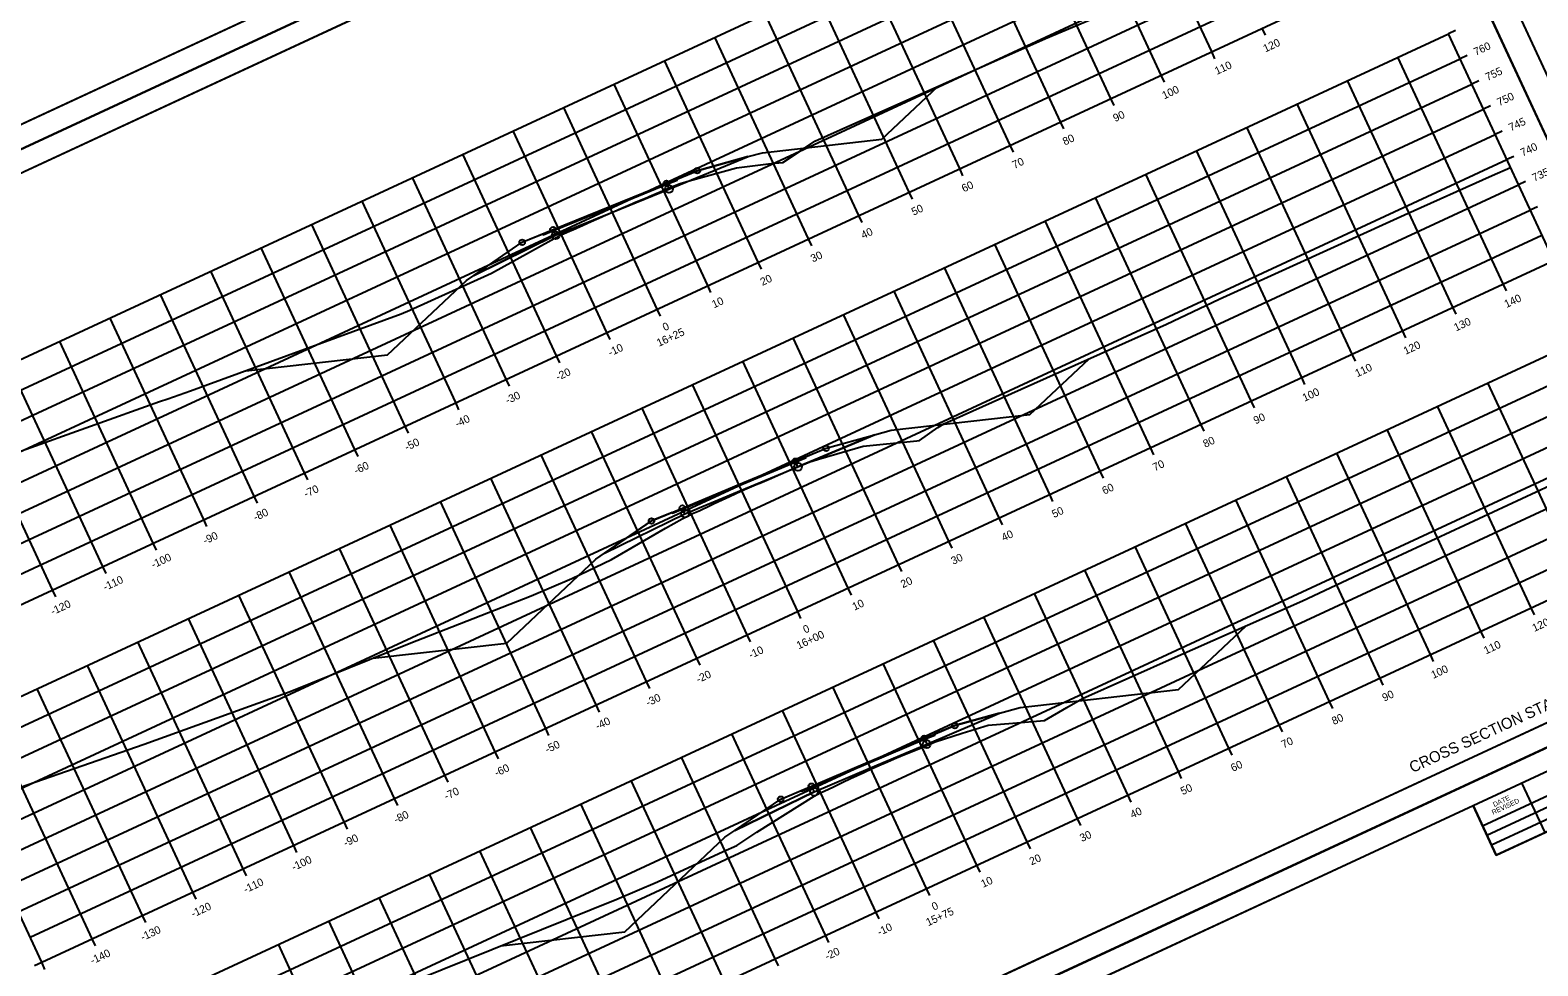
# Model space of a CAD drawing. Extents: x 1354696 to 1366163, y 660729 to 670380.
# Drawn here: x 1358666.2 to 1358937.5, y 666178.8 to 666347.2 of the extents above; entities that cross this region are included whole.
import ezdxf

# ---------------------------------------------------------------- set-up
doc = ezdxf.new("R2010")
doc.units = 0
for name, color, linetype in [('R_Alt Surface', 7, 'Continuous'), ('R_Axis', 7, 'Continuous'), ('R_Axis Annot', 7, 'Continuous'), ('R_Border', 7, 'Continuous'), ('R_Draft', 7, 'Continuous'), ('R_Exist Surface', 7, 'Continuous'), ('R_Fin Surface', 7, 'Continuous'), ('R_Grid', 7, 'Continuous'), ('R_No Plot', 7, 'Continuous')]:
    doc.layers.add(name, color=color, linetype=linetype)

msp = doc.modelspace()

# ---------------------------------------------------------------- linework, layer by layer
at = {"layer": 'R_Alt Surface'}
for p, q in [((1358780.65, 666319.63), (1358782.5, 666320.38)), ((1358780.72, 666319.47), (1358782.57, 666320.23)), ((1358758.42, 666310.55), (1358760.26, 666311.3)), ((1358758.49, 666310.39), (1358760.33, 666311.15)), ((1358803.86, 666269.64), (1358805.7, 666270.41)), ((1358803.93, 666269.49), (1358805.77, 666270.26)), ((1358781.69, 666260.42), (1358783.53, 666261.19)), ((1358781.76, 666260.27), (1358783.6, 666261.03)), ((1358827.03, 666219.73), (1358828.88, 666220.5)), ((1358827.1, 666219.57), (1358828.96, 666220.34)), ((1358804.93, 666210.36), (1358806.76, 666211.14)), ((1358805, 666210.21), (1358806.83, 666210.98))]:
    msp.add_line(p, q, dxfattribs=at)
for points in [[(1358745.99, 666303.07), (1358760.73, 666310.28), (1358770.93, 666314.44), (1358781.12, 666318.61), (1358795.4, 666324.44)], [(1358760.26, 666311.3), (1358770.45, 666315.46), (1358780.65, 666319.63)], [(1358760.33, 666311.15), (1358770.53, 666315.31), (1358780.72, 666319.47)], [(1358769.49, 666253.07), (1358784, 666260.17), (1358794.16, 666264.39), (1358804.33, 666268.62), (1358818.11, 666274.36)], [(1358783.53, 666261.19), (1358793.69, 666265.41), (1358803.86, 666269.64)], [(1358783.6, 666261.03), (1358793.76, 666265.26), (1358803.93, 666269.49)], [(1358792.97, 666203.14), (1358807.24, 666210.12), (1358817.37, 666214.41), (1358827.5, 666218.7), (1358840.58, 666224.25)], [(1358806.76, 666211.14), (1358816.9, 666215.43), (1358827.03, 666219.73)], [(1358806.83, 666210.98), (1358816.97, 666215.28), (1358827.1, 666219.57)]]:
    msp.add_lwpolyline(points, dxfattribs=at)
for points in [[(1358782.5, 666320.38), (1358782.57, 666320.23), (1358780.72, 666319.47), (1358781.12, 666318.61), (1358795.4, 666324.44), (1358786.21, 666321.9)], [(1358758.42, 666310.55), (1358758.49, 666310.39), (1358760.33, 666311.15), (1358760.73, 666310.28), (1358745.99, 666303.07), (1358754.7, 666309.03)], [(1358805.7, 666270.41), (1358809.4, 666271.95), (1358818.11, 666274.36), (1358804.33, 666268.62), (1358803.93, 666269.49), (1358805.77, 666270.26)], [(1358781.69, 666260.42), (1358777.98, 666258.88), (1358769.49, 666253.07), (1358784, 666260.17), (1358783.6, 666261.03), (1358781.76, 666260.27)], [(1358828.88, 666220.5), (1358828.96, 666220.34), (1358827.1, 666219.57), (1358827.5, 666218.7), (1358840.58, 666224.25), (1358832.57, 666222.03)], [(1358804.93, 666210.36), (1358805, 666210.21), (1358806.83, 666210.98), (1358807.24, 666210.12), (1358792.97, 666203.14), (1358801.24, 666208.79)]]:
    msp.add_lwpolyline(points, close=True, dxfattribs=at)
at = {"layer": 'R_Axis'}
for p, q in [((1358642.97, 666233.85), (1358915.07, 666360.18)), ((1358888.45, 666346.28), (1358887.86, 666347.55)), ((1358922.66, 666347.16), (1358921.39, 666346.57)), ((1358940.34, 666305.76), (1358921.39, 666346.57)), ((1358879.38, 666342.07), (1358878.79, 666343.34)), ((1358924.76, 666342.63), (1358923.49, 666342.04)), ((1358870.31, 666337.85), (1358869.72, 666339.12)), ((1358926.87, 666338.09), (1358925.6, 666337.5)), ((1358861.24, 666333.64), (1358860.65, 666334.91)), ((1358928.97, 666333.56), (1358927.7, 666332.97)), ((1358852.17, 666329.43), (1358851.58, 666330.7)), ((1358931.08, 666329.02), (1358929.81, 666328.43)), ((1358843.1, 666325.22), (1358842.51, 666326.49)), ((1358834.03, 666321.01), (1358833.44, 666322.28)), ((1358933.19, 666324.49), (1358931.92, 666323.9)), ((1358935.29, 666319.95), (1358934.02, 666319.36)), ((1358824.96, 666316.8), (1358824.37, 666318.07)), ((1358815.89, 666312.59), (1358815.3, 666313.86)), ((1358937.4, 666315.42), (1358936.13, 666314.83)), ((1358806.82, 666308.38), (1358806.23, 666309.65)), ((1358668.23, 666179.43), (1358940.34, 666305.76)), ((1358797.75, 666304.17), (1358797.16, 666305.44)), ((1358788.68, 666299.96), (1358788.09, 666301.23)), ((1358931.86, 666300.28), (1358931.27, 666301.55)), ((1358779.61, 666295.74), (1358779.02, 666297.01)), ((1358922.79, 666296.07), (1358922.2, 666297.34)), ((1358770.54, 666291.53), (1358769.95, 666292.8)), ((1358913.72, 666291.86), (1358913.13, 666293.13)), ((1358761.47, 666287.32), (1358760.88, 666288.59)), ((1358904.65, 666287.65), (1358904.06, 666288.91)), ((1358752.4, 666283.11), (1358751.81, 666284.38)), ((1358895.58, 666283.43), (1358894.99, 666284.7)), ((1358743.33, 666278.9), (1358742.74, 666280.17)), ((1358886.51, 666279.22), (1358885.92, 666280.49)), ((1358734.26, 666274.69), (1358733.67, 666275.96)), ((1358877.44, 666275.01), (1358876.85, 666276.28)), ((1358725.19, 666270.48), (1358724.6, 666271.75)), ((1358868.37, 666270.8), (1358867.78, 666272.07)), ((1358859.3, 666266.59), (1358858.71, 666267.86)), ((1358716.12, 666266.27), (1358715.53, 666267.54)), ((1358707.05, 666262.06), (1358706.46, 666263.33)), ((1358850.23, 666262.38), (1358849.64, 666263.65)), ((1358841.16, 666258.17), (1358840.57, 666259.44)), ((1358697.98, 666257.85), (1358697.39, 666259.12)), ((1358688.91, 666253.63), (1358688.32, 666254.9)), ((1358691.39, 666129.54), (1358963.5, 666255.87)), ((1358832.09, 666253.96), (1358831.5, 666255.23)), ((1358679.84, 666249.42), (1358679.25, 666250.69)), ((1358823.02, 666249.75), (1358822.43, 666251.02)), ((1358670.77, 666245.21), (1358670.18, 666246.48)), ((1358813.95, 666245.53), (1358813.36, 666246.8)), ((1358936.88, 666241.97), (1358936.29, 666243.24)), ((1358804.88, 666241.32), (1358804.29, 666242.59)), ((1358795.81, 666237.11), (1358795.22, 666238.38)), ((1358927.81, 666237.76), (1358927.22, 666239.03)), ((1358786.74, 666232.9), (1358786.15, 666234.17)), ((1358918.74, 666233.55), (1358918.15, 666234.82)), ((1358777.67, 666228.69), (1358777.08, 666229.96)), ((1358909.67, 666229.34), (1358909.08, 666230.61)), ((1358768.59, 666224.48), (1358768.01, 666225.75)), ((1358900.6, 666225.13), (1358900.01, 666226.4)), ((1358759.52, 666220.27), (1358758.94, 666221.54)), ((1358891.53, 666220.92), (1358890.94, 666222.19)), ((1358668.23, 666179.43), (1358649.28, 666220.24)), ((1358750.45, 666216.06), (1358749.87, 666217.33)), ((1358882.46, 666216.7), (1358881.87, 666217.97)), ((1358873.39, 666212.49), (1358872.8, 666213.76)), ((1358741.38, 666211.85), (1358740.8, 666213.12)), ((1358732.31, 666207.64), (1358731.72, 666208.91)), ((1358864.32, 666208.28), (1358863.73, 666209.55)), ((1358855.25, 666204.07), (1358854.66, 666205.34)), ((1358723.24, 666203.42), (1358722.65, 666204.69)), ((1358714.17, 666199.21), (1358713.58, 666200.48)), ((1358846.18, 666199.86), (1358845.59, 666201.13)), ((1358705.1, 666195), (1358704.51, 666196.27)), ((1358837.11, 666195.65), (1358836.52, 666196.92)), ((1358696.03, 666190.79), (1358695.44, 666192.06)), ((1358828.04, 666191.44), (1358827.45, 666192.71)), ((1358686.96, 666186.58), (1358686.37, 666187.85)), ((1358818.97, 666187.23), (1358818.38, 666188.5)), ((1358677.89, 666182.37), (1358677.3, 666183.64)), ((1358809.9, 666183.02), (1358809.31, 666184.29)), ((1358666.96, 666178.84), (1358668.23, 666179.43)), ((1358668.82, 666178.16), (1358668.23, 666179.43)), ((1358800.83, 666178.81), (1358800.24, 666180.07))]:
    msp.add_line(p, q, dxfattribs=at)
at = {"layer": 'R_Border'}
for p, q in [((1358889.5, 666434.68), (1358602.72, 666301.53)), ((1358606.04, 666294.39), (1358892.82, 666427.53)), ((1358979.34, 666241.18), (1358892.82, 666427.53)), ((1358979.34, 666241.18), (1358692.56, 666108.03)), ((1358695.88, 666100.89), (1358982.66, 666234.03)), ((1358986.82, 666225.07), (1358930, 666198.69)), ((1358927.53, 666204.01), (1358945.26, 666212.24)), ((1358938.78, 666202.77), (1358934.62, 666211.73)), ((1358928.32, 666202.32), (1358946.04, 666210.55)), ((1358929.14, 666200.56), (1358946.86, 666208.79)), ((1358930, 666198.69), (1358925.84, 666207.65))]:
    msp.add_line(p, q, dxfattribs=at)
at = {"layer": 'R_Exist Surface'}
for points in [[(1358639.7, 666262.63), (1358689.42, 666280.37), (1358690.94, 666280.84), (1358695.04, 666282.27), (1358732.95, 666296.13), (1358734.5, 666296.83), (1358749.21, 666303.45), (1358753.2, 666305.66), (1358760.47, 666309.72), (1358761.74, 666310.36), (1358761.85, 666310.42), (1358763.66, 666311.2), (1358763.82, 666311.28), (1358766.32, 666312.4), (1358766.55, 666312.51), (1358769.05, 666313.61), (1358769.3, 666313.73), (1358771.78, 666314.83), (1358772.03, 666314.95), (1358774.53, 666315.99), (1358774.8, 666316.1), (1358777.29, 666317.14), (1358777.57, 666317.26), (1358780.8, 666318.66), (1358781.21, 666318.83), (1358781.43, 666318.93), (1358783.13, 666319.63), (1358784.74, 666320.08), (1358793.28, 666322.44), (1358799.51, 666323.2), (1358801.62, 666323.37), (1358806.42, 666326.55), (1358807.4, 666327.22), (1358811.94, 666329.25), (1358848.88, 666345.73), (1358869.14, 666354.3)], [(1358660.03, 666209.45), (1358686.69, 666218.71), (1358712.92, 666228.19), (1358734.39, 666236.79), (1358756.3, 666245.4), (1358763.62, 666248.5), (1358770.78, 666251.93), (1358780.5, 666257.57), (1358783.5, 666259.28), (1358783.72, 666259.39), (1358784.91, 666259.99), (1358785.34, 666260.21), (1358786.57, 666260.69), (1358788.65, 666261.71), (1358789.28, 666261.99), (1358791.36, 666262.98), (1358791.99, 666263.27), (1358794.07, 666264.23), (1358794.72, 666264.53), (1358796.82, 666265.41), (1358797.48, 666265.69), (1358799.57, 666266.6), (1358800.24, 666266.88), (1358801.21, 666267.3), (1358804.33, 666268.66), (1358805.89, 666269.32), (1358806.27, 666269.47), (1358808.05, 666269.97), (1358816.08, 666272.31), (1358825.75, 666273.29), (1358826.23, 666273.34), (1358829.52, 666275.67), (1358830.56, 666276.38), (1358844.53, 666282.61), (1358870.67, 666294.31), (1358880.14, 666298.77), (1358913.49, 666313.95), (1358929.29, 666321.04), (1358932.58, 666322.46)], [(1358735.71, 666176.28), (1358771.72, 666190.8), (1358779.07, 666193.93), (1358790.85, 666199.37), (1358793.33, 666200.48), (1358796.92, 666202.85), (1358807.23, 666209.35), (1358807.81, 666209.65), (1358808.33, 666209.92), (1358809.04, 666210.23), (1358810.76, 666211.03), (1358812.29, 666211.77), (1358813.82, 666212.51), (1358814.99, 666213.06), (1358816.17, 666213.6), (1358817.71, 666214.33), (1358818.88, 666214.86), (1358820.47, 666215.53), (1358821.64, 666216.03), (1358823.23, 666216.69), (1358825.46, 666217.59), (1358827.08, 666218.3), (1358827.95, 666218.66), (1358829, 666219.09), (1358833.87, 666220.66), (1358838.58, 666222.1), (1358843.02, 666222.47), (1358848.68, 666222.98), (1358852.72, 666225.29), (1358855.57, 666226.94), (1358872.24, 666234.33), (1358895.16, 666244.47), (1358906.25, 666249.72), (1358939.75, 666265.33)]]:
    msp.add_lwpolyline(points, dxfattribs=at)
at = {"layer": 'R_Fin Surface'}
for points in [[(1358704.95, 666285.89), (1358730.48, 666288.79), (1358744.66, 666302.16), (1358745.99, 666303.07), (1358754.7, 666309.03), (1358760.26, 666311.3), (1358770.45, 666315.46), (1358780.65, 666319.63), (1358786.21, 666321.9), (1358795.4, 666324.44), (1358797.94, 666325.14), (1358819.43, 666327.57), (1358829.51, 666337.09)], [(1358727.83, 666234.16), (1358751.92, 666236.89), (1358767.94, 666252.01), (1358769.49, 666253.07), (1358777.98, 666258.88), (1358783.53, 666261.19), (1358793.69, 666265.41), (1358803.86, 666269.64), (1358809.4, 666271.95), (1358818.11, 666274.36), (1358821.13, 666275.19), (1358846.07, 666278.02), (1358856.72, 666288.06)], [(1358750.81, 666182.37), (1358773.16, 666184.91), (1358791.19, 666201.93), (1358792.97, 666203.14), (1358801.24, 666208.79), (1358806.76, 666211.14), (1358816.9, 666215.43), (1358827.03, 666219.73), (1358832.57, 666222.03), (1358840.58, 666224.25), (1358844.3, 666225.27), (1358872.81, 666228.51), (1358884.93, 666239.95)]]:
    msp.add_lwpolyline(points, dxfattribs=at)
at = {"layer": 'R_Grid'}
for p, q in [((1358626.12, 666270.13), (1358898.23, 666396.46)), ((1358628.23, 666265.59), (1358900.33, 666391.93)), ((1358630.33, 666261.06), (1358902.44, 666387.39)), ((1358632.44, 666256.52), (1358904.54, 666382.86)), ((1358878.79, 666343.34), (1358861.95, 666379.62)), ((1358634.55, 666251.99), (1358906.65, 666378.32)), ((1358636.65, 666247.45), (1358908.76, 666373.78)), ((1358869.72, 666339.12), (1358852.88, 666375.41)), ((1358860.65, 666334.91), (1358843.81, 666371.19)), ((1358638.76, 666242.92), (1358910.86, 666369.25)), ((1358851.58, 666330.7), (1358834.74, 666366.98)), ((1358640.86, 666238.38), (1358912.97, 666364.71)), ((1358842.51, 666326.49), (1358825.67, 666362.77)), ((1358642.97, 666233.85), (1358915.07, 666360.18)), ((1358833.44, 666322.28), (1358816.6, 666358.56)), ((1358824.37, 666318.07), (1358807.53, 666354.35)), ((1358815.3, 666313.86), (1358798.46, 666350.14)), ((1358649.28, 666220.24), (1358921.39, 666346.57)), ((1358940.34, 666305.76), (1358921.39, 666346.57)), ((1358806.23, 666309.65), (1358789.39, 666345.93)), ((1358651.39, 666215.71), (1358923.49, 666342.04)), ((1358797.16, 666305.44), (1358780.32, 666341.72)), ((1358931.27, 666301.55), (1358912.32, 666342.36)), ((1358922.2, 666297.34), (1358903.25, 666338.15)), ((1358653.5, 666211.17), (1358925.6, 666337.5)), ((1358788.09, 666301.23), (1358771.25, 666337.51)), ((1358655.6, 666206.64), (1358927.7, 666332.97)), ((1358779.02, 666297.01), (1358762.18, 666333.3)), ((1358913.13, 666293.13), (1358894.18, 666333.94)), ((1358657.71, 666202.1), (1358929.81, 666328.43)), ((1358769.95, 666292.8), (1358753.11, 666329.08)), ((1358904.06, 666288.91), (1358885.11, 666329.73)), ((1358760.88, 666288.59), (1358744.04, 666324.87)), ((1358894.99, 666284.7), (1358876.04, 666325.52)), ((1358659.81, 666197.57), (1358931.92, 666323.9)), ((1358661.92, 666193.03), (1358934.02, 666319.36)), ((1358751.81, 666284.38), (1358734.97, 666320.66)), ((1358885.92, 666280.49), (1358866.97, 666321.31)), ((1358742.74, 666280.17), (1358725.9, 666316.45)), ((1358876.85, 666276.28), (1358857.9, 666317.1)), ((1358664.02, 666188.5), (1358936.13, 666314.83)), ((1358733.67, 666275.96), (1358716.83, 666312.24)), ((1358867.78, 666272.07), (1358848.83, 666312.89)), ((1358666.13, 666183.96), (1358938.23, 666310.29)), ((1358858.71, 666267.86), (1358839.76, 666308.68)), ((1358668.23, 666179.43), (1358940.34, 666305.76)), ((1358724.6, 666271.75), (1358707.75, 666308.03)), ((1358715.53, 666267.54), (1358698.68, 666303.82)), ((1358849.64, 666263.65), (1358830.69, 666304.46)), ((1358840.57, 666259.44), (1358821.62, 666300.25)), ((1358706.46, 666263.33), (1358689.61, 666299.61)), ((1358697.39, 666259.12), (1358680.54, 666295.4)), ((1358831.5, 666255.23), (1358812.55, 666296.04)), ((1358674.55, 666165.82), (1358946.65, 666292.15)), ((1358688.32, 666254.9), (1358671.47, 666291.18)), ((1358822.43, 666251.02), (1358803.48, 666291.83)), ((1358679.25, 666250.69), (1358662.4, 666286.97)), ((1358676.66, 666161.29), (1358948.76, 666287.62)), ((1358813.36, 666246.8), (1358794.41, 666287.62)), ((1358670.18, 666246.48), (1358653.33, 666282.76)), ((1358678.76, 666156.75), (1358950.87, 666283.08)), ((1358804.29, 666242.59), (1358785.34, 666283.41)), ((1358945.36, 666247.45), (1358928.51, 666283.73)), ((1358680.87, 666152.22), (1358952.97, 666278.55)), ((1358795.22, 666238.38), (1358776.27, 666279.2)), ((1358936.29, 666243.24), (1358919.44, 666279.52)), ((1358682.97, 666147.68), (1358955.08, 666274.01)), ((1358786.15, 666234.17), (1358767.2, 666274.99)), ((1358927.22, 666239.03), (1358910.37, 666275.31)), ((1358777.08, 666229.96), (1358758.13, 666270.78)), ((1358918.15, 666234.82), (1358901.3, 666271.1)), ((1358685.08, 666143.15), (1358957.18, 666269.48)), ((1358687.18, 666138.61), (1358959.29, 666264.94)), ((1358768.01, 666225.75), (1358749.06, 666266.57)), ((1358909.08, 666230.61), (1358892.23, 666266.89)), ((1358758.94, 666221.54), (1358739.99, 666262.35)), ((1358900.01, 666226.4), (1358883.16, 666262.68)), ((1358689.29, 666134.08), (1358961.39, 666260.41)), ((1358749.87, 666217.33), (1358730.92, 666258.14)), ((1358890.94, 666222.19), (1358874.09, 666258.47)), ((1358691.39, 666129.54), (1358963.5, 666255.87)), ((1358881.87, 666217.97), (1358865.02, 666254.25)), ((1358740.8, 666213.12), (1358721.85, 666253.93)), ((1358731.72, 666208.91), (1358712.78, 666249.72)), ((1358872.8, 666213.76), (1358855.95, 666250.04)), ((1358722.65, 666204.69), (1358703.71, 666245.51)), ((1358863.73, 666209.55), (1358846.88, 666245.83)), ((1358713.58, 666200.48), (1358694.64, 666241.3)), ((1358854.66, 666205.34), (1358837.81, 666241.62)), ((1358704.51, 666196.27), (1358685.56, 666237.09)), ((1358845.59, 666201.13), (1358828.74, 666237.41)), ((1358695.44, 666192.06), (1358676.49, 666232.88)), ((1358836.52, 666196.92), (1358819.67, 666233.2)), ((1358686.37, 666187.85), (1358667.42, 666228.67)), ((1358827.45, 666192.71), (1358810.6, 666228.99)), ((1358677.3, 666183.64), (1358658.35, 666224.46)), ((1358818.38, 666188.5), (1358801.53, 666224.78)), ((1358668.23, 666179.43), (1358649.28, 666220.24)), ((1358809.31, 666184.29), (1358792.46, 666220.57)), ((1358800.24, 666180.07), (1358783.39, 666216.36)), ((1358791.17, 666175.86), (1358774.32, 666212.14)), ((1358782.1, 666171.65), (1358765.25, 666207.93)), ((1358773.03, 666167.44), (1358756.18, 666203.72)), ((1358763.96, 666163.23), (1358747.11, 666199.51)), ((1358754.89, 666159.02), (1358738.04, 666195.3)), ((1358745.82, 666154.81), (1358728.97, 666191.09)), ((1358736.75, 666150.6), (1358719.9, 666186.88)), ((1358727.68, 666146.39), (1358710.83, 666182.67))]:
    msp.add_line(p, q, dxfattribs=at)
at = {"layer": 'R_No Plot'}
for p, q in [((1358593.15, 666292.7), (1358895.49, 666433.07)), ((1358593.15, 666292.7), (1358895.49, 666433.07)), ((1358682.99, 666099.2), (1358985.33, 666239.57)), ((1358682.99, 666099.2), (1358985.33, 666239.57))]:
    msp.add_line(p, q, dxfattribs=at)
for points in [[(1358503.31, 666486.2), (1358805.65, 666626.57), (1358895.49, 666433.07), (1358593.15, 666292.7)], [(1358728.37, 666586.39), (1358746.17, 666594.66), (1358750.33, 666585.69), (1358764.94, 666592.48), (1358785.98, 666602.25), (1358797.95, 666576.76), (1358819, 666586.53), (1358889.5, 666434.68), (1358602.72, 666301.53), (1358516.2, 666487.89)], [(1358593.15, 666292.7), (1358895.49, 666433.07), (1358985.33, 666239.57), (1358682.98, 666099.2)], [(1358818.21, 666392.89), (1358836.01, 666401.15), (1358840.17, 666392.19), (1358854.78, 666398.98), (1358875.82, 666408.75), (1358887.79, 666383.26), (1358908.84, 666393.03), (1358979.34, 666241.18), (1358692.56, 666108.03), (1358606.04, 666294.39)], [(1358682.98, 666099.2), (1358985.33, 666239.57), (1359075.16, 666046.07), (1358772.82, 665905.7)], [(1358908.05, 666199.39), (1358925.84, 666207.65), (1358930, 666198.69), (1358944.62, 666205.48), (1358965.66, 666215.25), (1358977.62, 666189.76), (1358998.67, 666199.53), (1359069.18, 666047.68), (1358782.4, 665914.53), (1358695.88, 666100.89)]]:
    msp.add_lwpolyline(points, close=True, dxfattribs=at)
for centre, radius in [((1358786.21, 666321.9), 0.5), ((1358780.65, 666319.63), 0.5), ((1358781.12, 666318.61), 0.7), ((1358760.26, 666311.3), 0.5), ((1358754.7, 666309.03), 0.5), ((1358760.73, 666310.28), 0.7), ((1358809.4, 666271.95), 0.5), ((1358803.86, 666269.64), 0.5), ((1358804.33, 666268.62), 0.7), ((1358783.53, 666261.19), 0.5), ((1358784, 666260.17), 0.7), ((1358777.98, 666258.88), 0.5), ((1358832.57, 666222.03), 0.5), ((1358827.03, 666219.73), 0.5), ((1358827.5, 666218.7), 0.7), ((1358806.76, 666211.14), 0.5), ((1358807.24, 666210.12), 0.7), ((1358801.24, 666208.79), 0.5)]:
    msp.add_circle(centre, radius, dxfattribs=at)

# ---------------------------------------------------------------- texts
at = {"layer": 'R_Axis Annot'}
for s, p in [('120', (1358888.44, 666343.18)), ('760', (1358926.33, 666342.58)), ('110', (1358879.73, 666339.14)), ('755', (1358928.43, 666338.05)), ('100', (1358870.25, 666334.74)), ('750', (1358930.54, 666333.51)), ('90', (1358861.43, 666330.65)), ('745', (1358932.64, 666328.98)), ('80', (1358852.36, 666326.44)), ('740', (1358934.75, 666324.44)), ('70', (1358843.29, 666322.22)), ('735', (1358936.86, 666319.91)), ('60', (1358834.19, 666318)), ('50', (1358825.15, 666313.8)), ('40', (1358816.08, 666309.59)), ('30', (1358807.01, 666305.38)), ('20', (1358797.94, 666301.17)), ('10', (1358789.23, 666297.13)), ('140', (1358931.84, 666297.18)), ('130', (1358922.77, 666292.97)), ('16+25', (1358779.31, 666290.2)), ('0', (1358780.37, 666293.01)), ('-10', (1358770.57, 666288.46)), ('120', (1358913.7, 666288.76)), ('110', (1358904.99, 666284.72)), ('-20', (1358761.14, 666284.08)), ('-30', (1358752.07, 666279.87)), ('100', (1358895.51, 666280.32)), ('-40', (1358743, 666275.66)), ('90', (1358886.7, 666276.23)), ('-50', (1358733.93, 666271.45)), ('80', (1358877.63, 666272.02)), ('-60', (1358724.83, 666267.23)), ('70', (1358868.56, 666267.8)), ('-70', (1358715.79, 666263.03)), ('60', (1358859.46, 666263.58)), ('-80', (1358706.72, 666258.82)), ('50', (1358850.42, 666259.38)), ('-90', (1358697.65, 666254.61)), ('40', (1358841.35, 666255.17)), ('-100', (1358688.32, 666250.28)), ('30', (1358832.28, 666250.96)), ('-110', (1358679.66, 666246.25)), ('20', (1358823.21, 666246.75)), ('-120', (1358670.23, 666241.88)), ('10', (1358814.5, 666242.71)), ('120', (1358936.86, 666238.88)), ('16+00', (1358804.47, 666235.74)), ('0', (1358805.64, 666238.59)), ('-10', (1358795.84, 666234.04)), ('110', (1358928.15, 666234.83)), ('100', (1358918.67, 666230.43)), ('-20', (1358786.41, 666229.66)), ('-30', (1358777.34, 666225.45)), ('90', (1358909.86, 666226.34)), ('80', (1358900.79, 666222.13)), ('-40', (1358768.27, 666221.24)), ('-50', (1358759.2, 666217.03)), ('70', (1358891.72, 666217.92)), ('-60', (1358750.1, 666212.81)), ('60', (1358882.62, 666213.69)), ('-70', (1358741.06, 666208.61)), ('50', (1358873.58, 666209.5)), ('-80', (1358731.99, 666204.4)), ('40', (1358864.51, 666205.29)), ('-90', (1358722.92, 666200.19)), ('30', (1358855.44, 666201.07)), ('-100', (1358713.59, 666195.85)), ('20', (1358846.37, 666196.86)), ('-110', (1358704.93, 666191.83)), ('10', (1358837.66, 666192.82)), ('-120', (1358695.5, 666187.46)), ('15+75', (1358827.77, 666185.91)), ('0', (1358828.8, 666188.71)), ('-10', (1358819, 666184.16)), ('-130', (1358686.43, 666183.24)), ('-140', (1358677.36, 666179.03)), ('-20', (1358809.57, 666179.78))]:
    msp.add_text(s, height=1.4, rotation=24.9042, dxfattribs=at).set_placement(p)
at = {"layer": 'R_Border'}
for s, p in [('REVISED', (1358929.44, 666205.97)), ('DATE', (1358929.65, 666207.37))]:
    msp.add_text(s, height=0.879, rotation=24.9042, dxfattribs=at).set_placement(p)
at = {"layer": 'R_Draft'}
msp.add_text('CROSS SECTION STA. 15+75 TO STA. 16+25', height=2, rotation=24.9042, dxfattribs=at).set_placement((1358914.93, 666213.48))

doc.saveas('drawing.dxf')
